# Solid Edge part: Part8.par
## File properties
Author: Vicky Raina
Template: Normal.par
Last saved by: MYPC
Revision: 38
Application: Solid Edge
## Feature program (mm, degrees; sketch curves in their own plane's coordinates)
sketch for "unnamed Protrusion 1" plane through (0, 0, 0) normal (0, 0, 1) x-axis (1, 0, 0)
  arc centre (32.4919, 0.608) radius 66.4976 from (-33.994, -0.6361) to (-18.3494, 43.4693) cw
  arc centre (0, 28) radius 24 from (-18.3494, 43.4693) to (18.3494, 43.4693) cw
  arc centre (-32.4919, 0.608) radius 66.4976 from (18.3494, 43.4693) to (33.994, -0.6361) cw
  arc centre (0, 0) radius 34 from (33.994, -0.6361) to (-33.994, -0.6361) cw
extrude "unnamed Protrusion 1" add finite 6 along -normal
sketch for "unnamed RevolvedProtrusion 1" plane through (0, 0, 0) normal (0, 0, 1) x-axis (1, 0, 0)
  line (0, 52) -> (0, -34)
  arc centre (0, 0) radius 34 from (0, -34) to (-33.994, -0.6361) cw
  arc centre (32.4919, 0.608) radius 66.4976 from (-33.994, -0.6361) to (-18.3494, 43.4693) cw
  arc centre (0, 28) radius 24 from (-18.3494, 43.4693) to (0, 52) cw
revolve "unnamed RevolvedProtrusion 1" add finite about sketch line (0, 51.9687) -> (0, 65.9821)
fillet "unnamed Round 1"
sketch for "unnamed Cutout 1" #1 plane through (0, 4, -6) normal (0, 0, -1) x-axis (-1, 0, 0)
  circle centre (13, -19) radius 2.5
sketch for "unnamed Cutout 1" #2 plane through (0, 4, -6) normal (0, 0, -1) x-axis (-1, 0, 0)
  circle centre (-13, -19) radius 2.5
  dimension (linear) = 13
extrude "unnamed Cutout 1" cut finite 3 along -normal
thinwall "unnamed Thinwall 1"
sketch for "unnamed Cutout 2" plane through (0, 0, 0) normal (0, 0, 1) x-axis (1, 0, 0)
  circle centre (0, 11) radius 8
extrude "unnamed Cutout 2" cut through along -normal
chamfer "unnamed Chamfer 1"
sketch for "unnamed Cutout 3" plane through (0, 0, 0) normal (0, -1, 0) x-axis (1, 0, 0)
  circle centre (0, 0) radius 3
extrude "unnamed Cutout 3" cut through along -normal
sketch for "unnamed Protrusion 2" plane through (0, 0, 1) normal (0, 0, 1) x-axis (1, 0, 0)
  circle centre (-13, -15) radius 2.5
extrude "unnamed Protrusion 2" add through along +normal
mirror "unnamed Mirror 1" of "unnamed Protrusion 2" about plane through (0, 0, 0) normal (1, 0, 0)
extrude "unnamed Protrusion 3" add through
web network "unnamed WebNetwork 1"
rib "unnamed Rib 1"
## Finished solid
Body 1: sheet body, 1 face, 4 edges, 4 vertices.
  Faces by surface: plane 1
  Edges by curve: line 4
Body 2: sheet body, 1 face, 2 edges, 0 vertices.
  Faces by surface: cylinder 1
  Edges by curve: circle 2
Body 3: sheet body, 1 face, 3 edges, 2 vertices.
  Faces by surface: swept 1
  Edges by curve: ellipse 2, line 1
Body 4: solid body, 67 faces, 159 edges, 96 vertices.
  Faces by surface: plane 39, cylinder 13, torus 10, sphere 4, cone 1
  Edges by curve: circle 71, line 67, intersection 21
Bounding box of the edges (mm; curved faces can reach further): 139.700 x 105.279 x 54.293, from (-69.85, -45.1917, -6) to (69.85, 60.0873, 48.2926).
Cylindrical faces by radius (mm): R2.5 x6, R3 x1, R4.5 x2, R8 x1, R10.5 x1, R12.5 x2, R14 x1
Conical faces (half-angle, radius in mm at the cone's reference point): 45 deg R8 x1
Toroidal faces (ring radius, tube radius in mm): R-32.4919 r64.4976 x1, R-32.4919 r66.4976 x1, R18 r4 x1, R18 r6 x1, R28 r4 x1, R28 r6 x1, R60.4976 r4 x2, R60.4976 r6 x2
Spherical faces by radius (mm): R22 x1, R24 x1, R32 x1, R34 x1
Planar faces by outward normal: +x 5, +y 7, +z 10, -x 4, -y 8, -z 5
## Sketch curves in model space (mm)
arc centre (-28, -15, 1) radius 12.5 from (-15.5, -15, 1) through (-17.1245, -15, 7.1623) to (-21.5758, -15, 11.7228)
line (-10.5, -15, 1) -> (-15.5, -15, 1)
arc centre (0, -15, 1) radius 10.5 from (10.5, -15, 1) through (-0.3111, -15, 11.4954) to (-10.5, -15, 1)
line (15.5, -15, 1) -> (10.5, -15, 1)
arc centre (28, -15, 1) radius 12.5 from (21.5758, -15, 11.7228) through (17.1245, -15, 7.1623) to (15.5, -15, 1)
line (0, -0.5987, 0) -> (0, -32, 0)
line (0, 49.7945, 0) -> (0, 42.1802, 0)
line (0, 42.1802, 0) -> (0, -0.5987, 0)
line (0, -34, 0) -> (0, -45.1917, 0)
line (0, -0.6361, 0) -> (0, -34, 0)
line (0, 51.8118, 0) -> (0, 60.0873, 0)
line (0, 43.4693, 0) -> (0, 51.8118, 0)
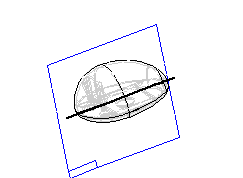
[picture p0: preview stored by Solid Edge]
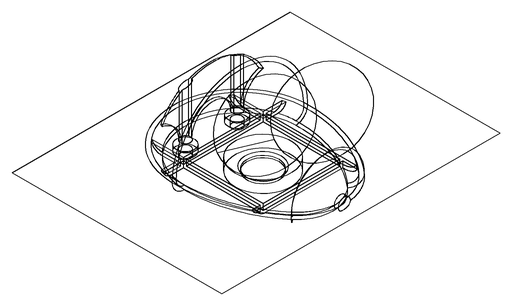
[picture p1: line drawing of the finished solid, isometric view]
